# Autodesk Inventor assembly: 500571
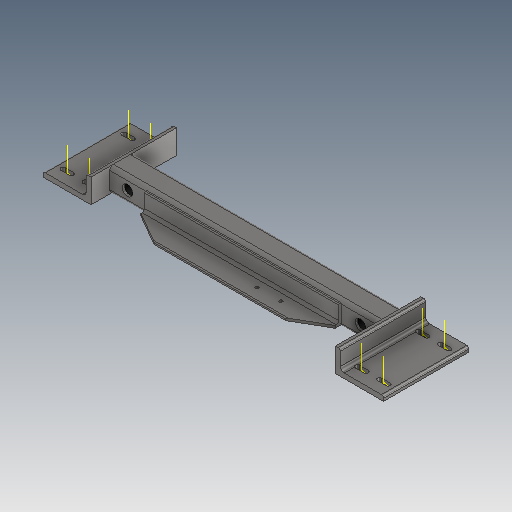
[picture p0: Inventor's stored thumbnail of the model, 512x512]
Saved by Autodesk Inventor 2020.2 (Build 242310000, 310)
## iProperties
Created: 2000-02
Part Number: 500571
Description: WMT-CP,TU,XX,297,050,030,SLIDE_BASE
Document SubType Name: Assembly
Designer: cmcgourin
Mass: 8820.75 g
Surface Area: 3684.7 cm^2
Volume: 1123.66 cm^3
Density: 7.85 g/cm^3
Control State: 0
Checked Out: False
Master: False
Shininess: 0.0
Length Units: 11269
Angle Units: 11279
Time Units: 11290
Mass Units: 11283
Length Display Precision: 3
Angle Display Precision: 2
Compacted: True
Cutlength: 21.75
Material Desc: TUBE,SQ,STL,2.00X2.00X0.25
Material_Number: A084675
Dimensions: 760x228x50 mm
Mass: 8,821 kg
DocNumber: 500571.iam
Folder: 01 - Themengebiete\Simplification\01 - Packaging machine\
VDS_Category: 3D Komponenten
Density: 0.0
Volumn: 0.0
Area: 0.0
PropertySet Name: Model Information
_SolveAssemblyDoc: Frame Generator Solve Assembly
_Version: 15.0.0
Author: cmcgourin
Revision Number: -
Title: WMT-CP,TU,XX,297,050,030,SLIDE_BASE
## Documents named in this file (3)
- D:\07 - DEMODATEN\OTX 2019 - Dataset - UPDATE - Dez2019\Designs\07-Packing machine\500571.iam
- D:\07 - DEMODATEN\OTX 2019 - Dataset - UPDATE - Dez2019\Designs\07-Packing machine\Parts\ADSK-014319.ipt
- D:\07 - DEMODATEN\OTX 2019 - Dataset - UPDATE - Dez2019\Designs\07-Packing machine\500571\Frame\ADSK-014320.iam
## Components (2 placed, 2 different names)
1. ADSK-014319:1 — Fluchtend:6, Fluchtend:7, Fluchtend:8
2. ADSK-014320:1 [sub-assembly]
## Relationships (3: Flush 3)
- Fluchtend:6 [Flush]: ADSK-014319:1
- Fluchtend:7 [Flush]: ADSK-014319:1
- Fluchtend:8 [Flush]: ADSK-014319:1
